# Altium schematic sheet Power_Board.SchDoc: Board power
size A3; Project: STM32MP15-DISCO; Date: Not used; ApprovedBy: Not used; CheckedBy: Not used; Author: Not used; CompanyName: STMicroelectronics; DrawnBy: Not used; Engineer: Not used; Organization: Not used; Address1: Not used; Address2: Not used; Address3: Not used; Address4: Not used; DocumentNumber: 5; Revision: Not used; SheetNumber: 5; SheetTotal: 17
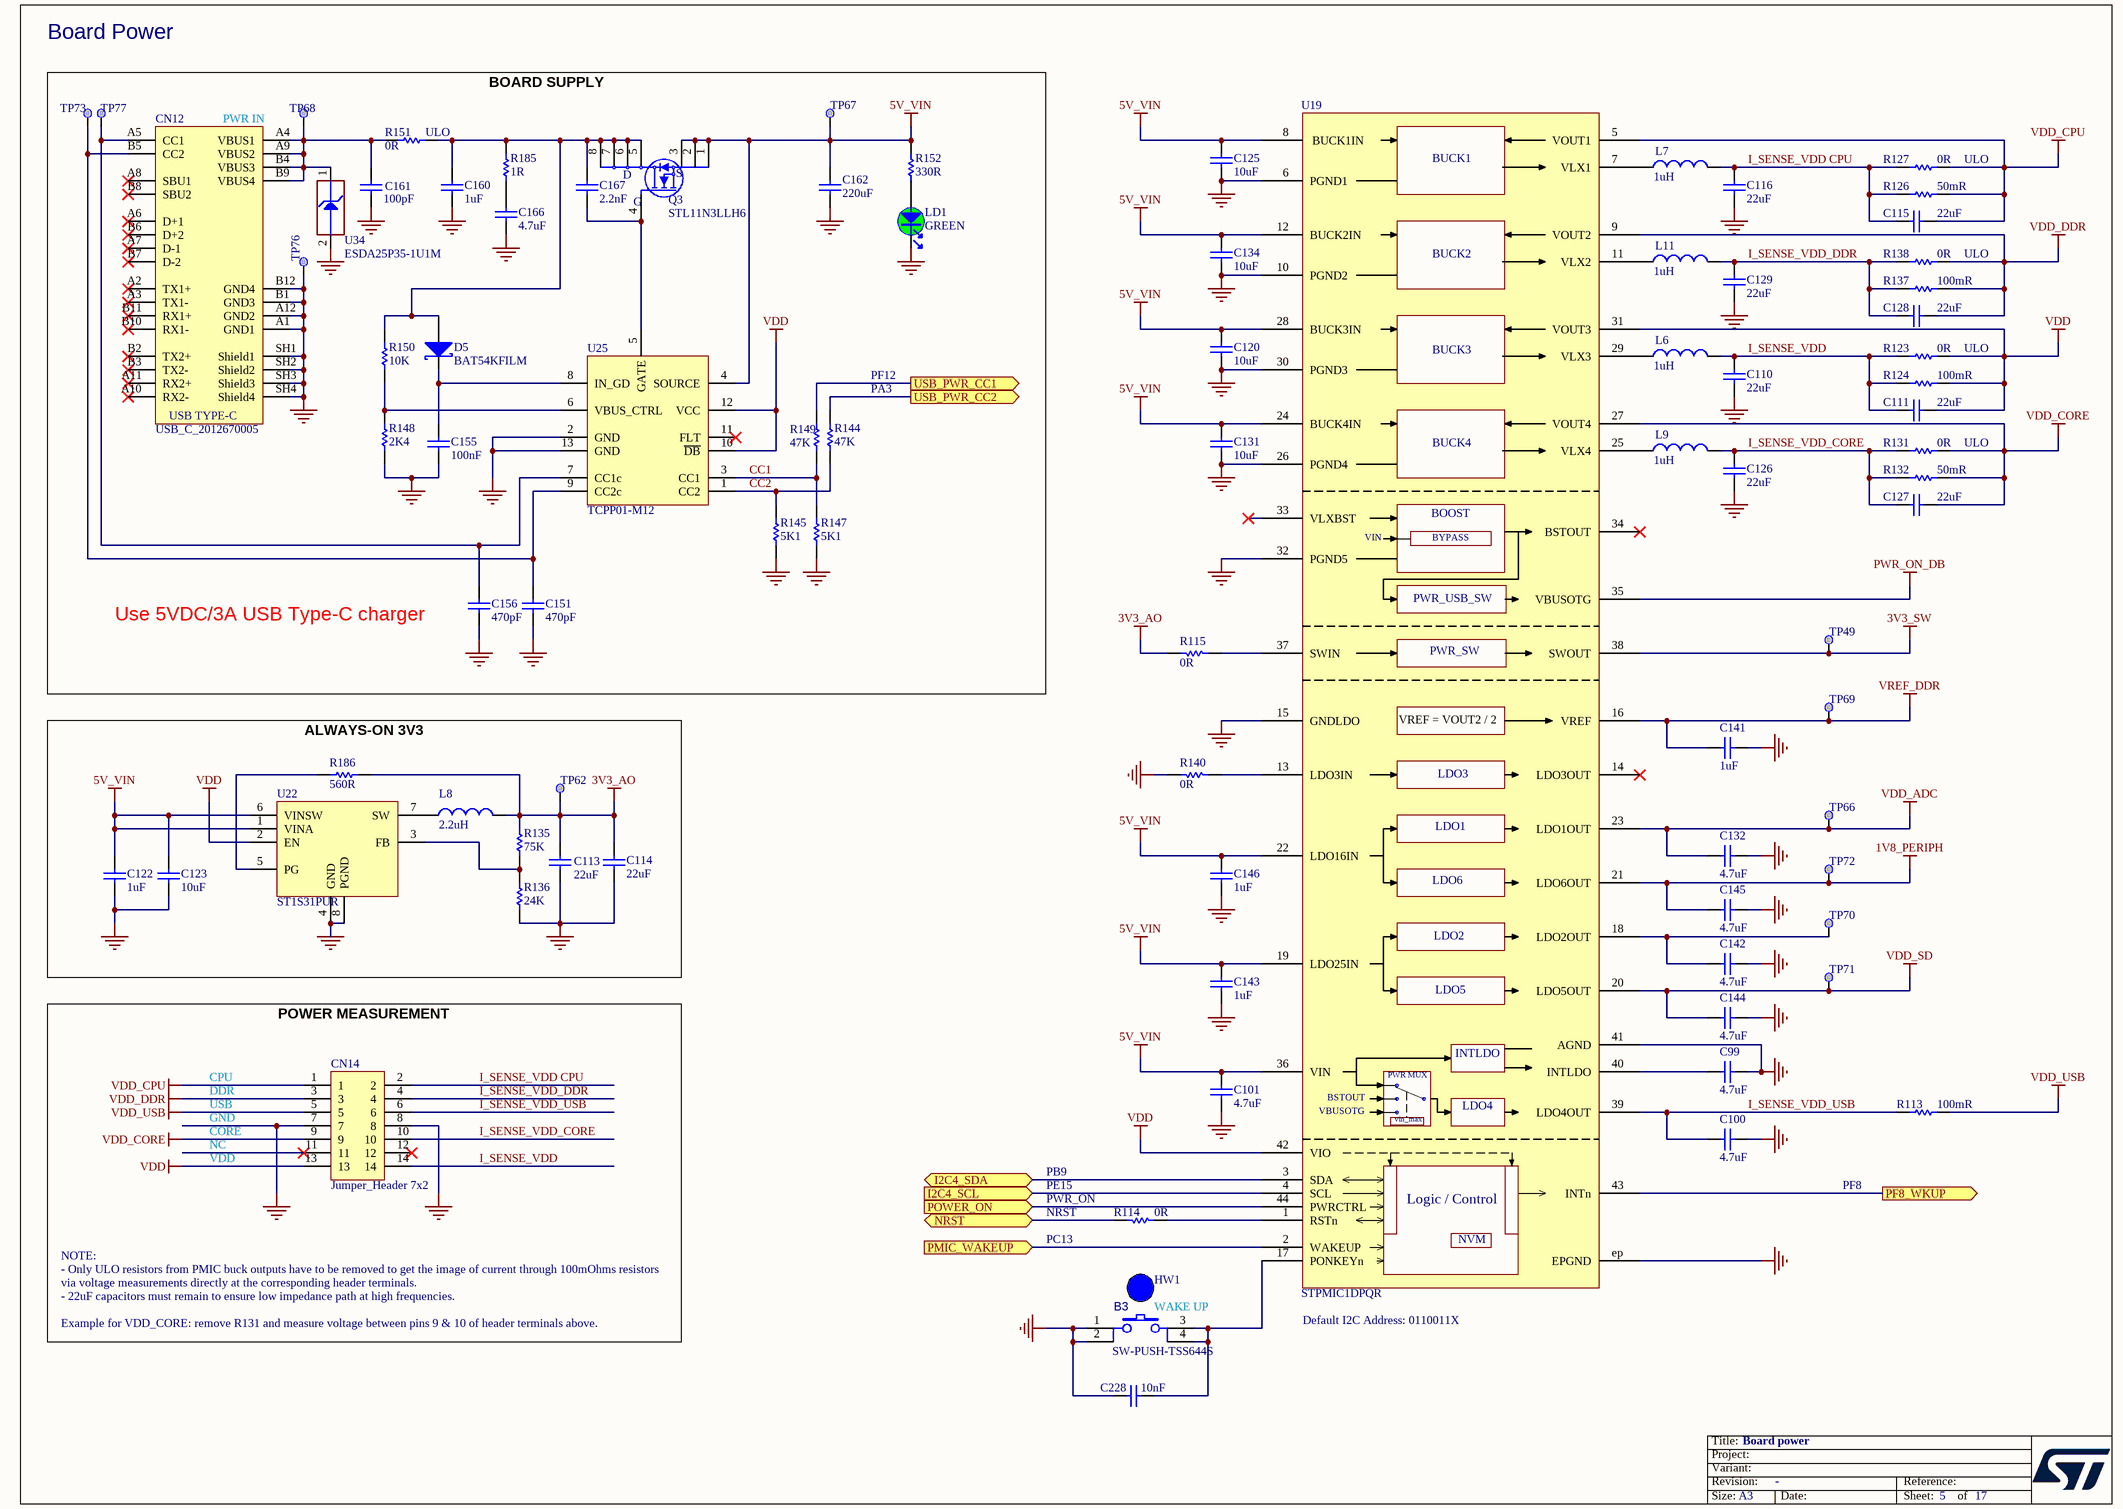
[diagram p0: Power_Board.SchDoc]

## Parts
B3  value SW-PUSH-TSS644S  [SWI_KNITTER_TSS644S]  (hidden comment: SW_PUSH_SMD)
C99  value 4.7uF  [C0402]  (hidden comment: Capacitor)
C100  value 4.7uF  [C0402]  (hidden comment: Capacitor)
C101  value 4.7uF  [C0402]  (hidden comment: Capacitor)
C110  value 22uF  [C0603]  (hidden comment: Capacitor)
C111  value 22uF  [C0603]  (hidden comment: Capacitor)
C113  value 22uF  [C0603]  (hidden comment: Capacitor)
C114  value 22uF  [C0603]  (hidden comment: Capacitor)
C115  value 22uF  [C0603]  (hidden comment: Capacitor)
C116  value 22uF  [C0603]  (hidden comment: Capacitor)
C120  value 10uF  [C0603]  (hidden comment: Capacitor)
C122  value 1uF  [C0402]  (hidden comment: Capacitor)
C123  value 10uF  [C0603]  (hidden comment: Capacitor)
C125  value 10uF  [C0603]  (hidden comment: Capacitor)
C126  value 22uF  [C0603]  (hidden comment: Capacitor)
C127  value 22uF  [C0603]  (hidden comment: Capacitor)
C128  value 22uF  [C0603]  (hidden comment: Capacitor)
C129  value 22uF  [C0603]  (hidden comment: Capacitor)
C131  value 10uF  [C0603]  (hidden comment: Capacitor)
C132  value 4.7uF  [C0402]  (hidden comment: Capacitor)
C134  value 10uF  [C0603]  (hidden comment: Capacitor)
C141  value 1uF  [C0402]  (hidden comment: Capacitor)
C142  value 4.7uF  [C0402]  (hidden comment: Capacitor)
C143  value 1uF  [C0402]  (hidden comment: Capacitor)
C144  value 4.7uF  [C0402]  (hidden comment: Capacitor)
C145  value 4.7uF  [C0402]  (hidden comment: Capacitor)
C146  value 1uF  [C0402]  (hidden comment: Capacitor)
C151  value 470pF  [C0402]  (hidden comment: Capacitor)
C155  value 100nF  [C0603]  (hidden comment: Capacitor)
C156  value 470pF  [C0402]  (hidden comment: Capacitor)
C160  value 1uF  [C0402]  (hidden comment: Capacitor)
C161  value 100pF  [C0402]  (hidden comment: Capacitor)
C162  value 220uF  [C1206_H1P6]  (hidden comment: Capacitor)
C166  value 4.7uF  [C0603]  (hidden comment: Capacitor)
C167  value 2.2nF  [C0603_H0P8]  (hidden comment: Capacitor)
C228  value 10nF  [C0402]  (hidden comment: Capacitor)
CN12  value USB_C_2012670005  [CON_USB-TYPEC_MOLEX_2012670005]  (hidden comment: USB_TYPE_C_Receptacle)
CN14  value Jumper_Header 7x2  [CON_SAMTEC_TSW-107-07-X-D]  (hidden comment: Header 7x2)
D5  value BAT54KFILM  [DIO_SOD523_1A_2K]  (hidden comment: SCHOTTKY_1A_2K)
HW1  Blue Hat  (value not drawn)  (mechanical)
L6  value 1uH  [IND_2520_TOKO_DFE252012P]  (hidden comment: IND_1uH_42mohm_3.2A)
L7  value 1uH  [IND_2520_TOKO_DFE252012P]  (hidden comment: IND_1uH_42mohm_3.2A)
L8  value 2.2uH  [IND_4025_WURTH_74404043022A]  (hidden comment: Inductor)
L9  value 1uH  [IND_2520_TOKO_DFE252012P]  (hidden comment: IND_1uH_42mohm_3.2A)
L11  value 1uH  [IND_2520_TOKO_DFE252012P]  (hidden comment: IND_1uH_42mohm_3.2A)
LD1  value GREEN  [LED_0603_GREEN]  (hidden comment: LED_green)
Q3  STL11N3LLH6  [MOS_POWERFLAT_3P3X3P3_P065]
R113  value 100mR  [R0603]  (hidden comment: Resistor)
R114  value 0R  [R0402]  (hidden comment: Resistor)
R115  value 0R  [R0402]  (hidden comment: Resistor)
R123  value 0R  [R0603]  (hidden comment: Resistor)
R124  value 100mR  [R0603]  (hidden comment: Resistor)
R126  value 50mR  [R0603]  (hidden comment: Resistor)
R127  value 0R  [R0603]  (hidden comment: Resistor)
R131  value 0R  [R0603]  (hidden comment: Resistor)
R132  value 50mR  [R0603]  (hidden comment: Resistor)
R135  value 75K  [R0402]  (hidden comment: Resistor)
R136  value 24K  [R0402]  (hidden comment: Resistor)
R137  value 100mR  [R0603]  (hidden comment: Resistor)
R138  value 0R  [R0603]  (hidden comment: Resistor)
R140  value 0R  [R0402]  (hidden comment: Resistor)
R144  value 47K  [R0402]  (hidden comment: Resistor)
R145  value 5K1  [R0402]  (hidden comment: Resistor)
R147  value 5K1  [R0402]  (hidden comment: Resistor)
R148  value 2K4  [R0402]  (hidden comment: Resistor)
R149  value 47K  [R0402]  (hidden comment: Resistor)
R150  value 10K  [R0402]  (hidden comment: Resistor)
R151  value 0R  [R0603]  (hidden comment: Resistor)
R152  value 330R  [R0402]  (hidden comment: Resistor)
R185  value 1R  [R0603]  (hidden comment: Resistor)
R186  value 560R  [R0402]  (hidden comment: Resistor)
TP49  Test Point  [TP_SMD_1MM]  (value not drawn)  (no BOM)
TP62  Test Point  [TP_SMD_1MM]  (value not drawn)  (no BOM)
TP66  Test Point  [TP_SMD_1MM]  (value not drawn)  (no BOM)
TP67  Test Point  [TP_SMD_1MM]  (value not drawn)  (no BOM)
TP68  Test Point  [TP_SMD_2MM]  (value not drawn)  (no BOM)
TP69  Test Point  [TP_SMD_1MM]  (value not drawn)  (no BOM)
TP70  Test Point  [TP_SMD_1MM]  (value not drawn)  (no BOM)
TP71  Test Point  [TP_SMD_1MM]  (value not drawn)  (no BOM)
TP72  Test Point  [TP_SMD_1MM]  (value not drawn)  (no BOM)
TP73  Test Point  [TP_SMD_1MM]  (value not drawn)  (no BOM)
TP76  Test Point  [TP_SMD_2MM]  (value not drawn)  (no BOM)
TP77  Test Point  [TP_SMD_1MM]  (value not drawn)  (no BOM)
U19  value STPMIC1DPQR  [ICC_WFQFN44-EPAD_5X6_P040]  (hidden comment: STPMU1)
U22  ST1S31PUR  [ICC_VFDFPN8-EPAD_3X3_P065]
U25  TCPP01-M12  [ICC_QFN12L-EPAD_3X3_P050]
U34  value ESDA25P35-1U1M  [ESD_QFN1610_2N_1K_2A]  (hidden comment: ESD-TRANSIL)

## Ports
I2C4_SCL (in), I2C4_SDA (bidir), NRST (bidir), PF8_WKUP (out), PMIC_WAKEUP (in), POWER_ON (in), USB_PWR_CC1 (out), USB_PWR_CC2 (out)

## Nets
1V8_PERIPH: C145.2 TP72.1 U19.21(LDO6OUT)
3V3_AO: C113.2 C114.2 L8.2 R115.1 R135.2 R186.2 TP62.1
3V3_SW: TP49.1 U19.38(SWOUT)
5V_VIN: C101.2 C120.2 C122.2 C123.2 C125.2 C131.2 C134.2 C143.2 C146.2 C162.1 Q3.1(S) Q3.2(S) Q3.3(S) R152.2 TP67.1 U19.8(BUCK1IN) U19.12(BUCK2IN) U19.19(LDO25IN) U19.22(LDO16IN) U19.24(BUCK4IN) U19.28(BUCK3IN) U19.36(VIN) U22.1(VINA) U22.6(VINSW) U25.4(SOURCE)
GND: B3.1 B3.2 C99.2 C100.1 C101.1 C110.1 C113.1 C114.1 C116.1 C120.1 C122.1 C123.1 C125.1 C126.1 C129.1 C131.1 C132.1 C134.1 C141.1 C142.1 C143.1 C144.1 C145.1 C146.1 C151.1 C155.2 C156.1 C160.2 C161.1 C162.2 C166.1 C228.1 CN12.A1(GND1) CN12.A12(GND2) CN12.B1(GND3) CN12.B12(GND4) CN12.SH1(Shield1) CN12.SH2(Shield2) CN12.SH3(Shield3) CN12.SH4(Shield4) CN14.7 CN14.8 LD1.2 R136.1 R140.1 R145.1 R147.1 R148.1 TP76.1 U19.6(PGND1) U19.10(PGND2) U19.15(GNDLDO) U19.26(PGND4) U19.30(PGND3) U19.32(PGND5) U19.41(AGND) U19.ep(EPGND) U22.4(GND) U22.8(PGND) U25.2(GND) U25.13(GND) U34.2(GND)
PWR_ON_DB: U19.35(VBUSOTG)
VDD: C111.2 CN14.13 R123.2 R124.2 U19.31(VOUT3) U19.42(VIO) U22.2(EN) U25.10(~{DB}) U25.12(VCC)
VDD_ADC: C132.2 TP66.1 U19.23(LDO1OUT)
VDD_CORE: C127.2 CN14.9 R131.2 R132.2 U19.27(VOUT4)
VDD_CPU: C115.2 CN14.1 R126.2 R127.2 U19.5(VOUT1)
VDD_DDR: C128.2 CN14.3 R137.2 R138.2 U19.9(VOUT2)
VDD_SD: C144.2 TP71.1 U19.20(LDO5OUT)
VDD_USB: CN14.5 R113.2
VREF_DDR: C141.2 TP69.1 U19.16(VREF)
CC1: R147.2 R149.1 U25.3(CC1)
CC2: R144.1 R145.2 U25.1(CC2)
I2C4_SCL: U19.4(SCL) ; port I2C4_SCL
I2C4_SDA: U19.3(SDA) ; port I2C4_SDA
I_SENSE_VDD: C110.2 C111.1 CN14.14 L6.2 R123.1 R124.1
I_SENSE_VDD CPU: C115.1 C116.2 CN14.2 L7.2 R126.1 R127.1
I_SENSE_VDD_CORE: C126.2 C127.1 CN14.10 L9.2 R131.1 R132.1
I_SENSE_VDD_DDR: C128.1 C129.2 CN14.4 L11.2 R137.1 R138.1
I_SENSE_VDD_USB: C100.2 CN14.6 R113.1 U19.39(LDO4OUT)
NRST: R114.1 ; port NRST
PF8_WKUP: U19.43(INTn) ; port PF8_WKUP
PMIC_WAKEUP: U19.2(WAKEUP) ; port PMIC_WAKEUP
POWER_ON: U19.44(PWRCTRL) ; port POWER_ON
USB_PWR_CC1: R149.2 ; port USB_PWR_CC1
USB_PWR_CC2: R144.2 ; port USB_PWR_CC2
NetB3_3: B3.3 B3.4 C228.2 U19.17(PONKEYn)
NetC99_1: C99.1 U19.40(INTLDO)
NetC142_2: C142.2 TP70.1 U19.18(LDO2OUT)
NetC151_2: C151.2 CN12.B5(CC2) TP73.1 U25.9(CC2c)
NetC155_1: C155.1 D5.2(K) U25.8(IN_GD)
NetC156_2: C156.2 CN12.A5(CC1) TP77.1 U25.7(CC1c)
NetC160_1: C160.1 C167.2 D5.1(A) Q3.5(D) Q3.6(D) Q3.7(D) Q3.8(D) R150.2 R151.2 R185.2
NetC161_2: C161.2 CN12.A4(VBUS1) CN12.A9(VBUS2) CN12.B4(VBUS3) CN12.B9(VBUS4) R151.1 TP68.1 U34.1(IO1)
NetC166_2: C166.2 R185.1
NetC167_1: C167.1 Q3.4(G) U25.5(GATE)
NetL6_1: L6.1 U19.29(VLX3)
NetL7_1: L7.1 U19.7(VLX1)
NetL8_1: L8.1 U22.7(SW)
NetL9_1: L9.1 U19.25(VLX4)
NetL11_1: L11.1 U19.11(VLX2)
NetLD1_1: LD1.1 R152.1
NetR114_2: R114.2 U19.1(RSTn)
NetR115_2: R115.2 U19.37(SWIN)
NetR135_1: R135.1 R136.2 U22.3(FB)
NetR140_2: R140.2 U19.13(LDO3IN)
NetR148_2: R148.2 R150.1 U25.6(VBUS_CTRL)
NetR186_1: R186.1 U22.5(PG)

Not connected (* = marked no-connect by the designer): CN12 A2(TX1+)* A3(TX1-)* A6(D+1)* A7(D-1)* A8(SBU1)* A10(RX2-)* A11(RX2+)* B2(TX2+)* B3(TX2-)* B6(D+2)* B7(D-2)* B8(SBU2)* B10(RX1-)* B11(RX1+)*; CN14 11* 12*; U19 14(LDO3OUT)* 33(VLXBST)* 34(BSTOUT)*; U25 11(FLT)*

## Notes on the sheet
- Board Power
- (near CN12) PWR IN
- (near R151) ULO
- ULO
- PF12
- PA3
- Use 5VDC/3A USB Type-C charger
- BOARD SUPPLY
- ALWAYS-ON 3V3
- CPU
- DDR
- USB
- GND
- VDD
- CORE
- NC
- PB9
- PE15
- PF8
- NRST
- (near R114) PWR_ON
- PC13
- NOTE:
  - Only ULO resistors from PMIC buck outputs have to be removed to get the image of current through 100mOhms resistors via voltage measurements directly at the corresponding header terminals.
  - 22uF capacitors must remain to ensure low impedance path at high frequencies.
  Example for VDD_CORE: remove R131 and measure voltage between pins 9 & 10 of header terminals above.
- (near B3) WAKE UP
- Default I2C Address: 0110011X
- (near CN14) POWER MEASUREMENT

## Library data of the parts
B3 = MCD-02417: Push Button, NO, 0.05A, 12V, 2.6N, SMD, 9.0x6.2mm, T=7.3mm, changeable caps KTSC-6xx; Part_Type: Misc; Manufacturer_Part_Number: TSS644S; Manufacturer: KNITTER-SWITCH; Part_Preference: Recommended; Component_Country_Of_Origin: China; ShowFields: YES; ID: 4523
C99-C101 C132 C142 C144 C145 = MCD-01356: Capacitor, MLCC, 4.7uF, 6V3, X5R, +/-20%, 0402, T=0.5mm; Manufacturer_Part_Number: GRM155R60J475ME47; Manufacturer: MURATA; Part_Preference: Recommended; Order_Code_RS: 814-5230; Component_Country_Of_Origin: Japan; ShowFields: YES; ID: 3456
C110 C116 C126 C129 = MCD-00100: Capacitor, MLCC, 22uF, 6V3, X5R, +/-20%, 0603, T=0.8mm; Manufacturer_Part_Number: GRM188R60J226MEA0J; Manufacturer: MURATA; Part_Preference: Recommended; Component_Country_Of_Origin: Japan; ShowFields: YES; ID: 2766
C111 C113-C115 C127 C128 = MCD-00100: Capacitor, MLCC, 22uF, 6V3, X5R, +/-20%, 0603, T=0.8mm; Part_Preference: Recommended; Manufacturer: MURATA; Manufacturer_Part_Number: GRM188R60J226MEA0J; Component_Country_Of_Origin: Japan; ShowFields: YES; ID: 2766
C120 C125 C131 C134 = MCD-00099: Capacitor, MLCC, 10uF, 10V, X5R, +/-10%, 0603, T=0.8mm; Manufacturer_Part_Number: GRM188R61A106KE69D; Manufacturer: MURATA; Part_Preference: Recommended; Order_Code_RS: 170-6168; Component_Country_Of_Origin: Japan; ShowFields: YES; ID: 2770
C122 = MCD-00095: Capacitor, MLCC, 1uF, 25V, X5R, +/-10%, 0402, T=0.5mm; Part_Preference: Recommended; Manufacturer: MURATA; Manufacturer_Part_Number: GRM155R61E105KA12; Order_Code_RS: 846-7287; Component_Country_Of_Origin: Japan; ShowFields: YES; ID: 2772
C123 = MCD-00099: Capacitor, MLCC, 10uF, 10V, X5R, +/-10%, 0603, T=0.8mm; Part_Preference: Recommended; Manufacturer: MURATA; Manufacturer_Part_Number: GRM188R61A106KE69D; Order_Code_RS: 170-6168; Component_Country_Of_Origin: Japan; ShowFields: YES; ID: 2770
C141 C143 C146 C160 = MCD-00095: Capacitor, MLCC, 1uF, 25V, X5R, +/-10%, 0402, T=0.5mm; Manufacturer_Part_Number: GRM155R61E105KA12; Manufacturer: MURATA; Part_Preference: Recommended; Order_Code_RS: 846-7287; Component_Country_Of_Origin: Japan; ShowFields: YES; ID: 2772
C151 C156 = MCD-00724: Capacitor, MLCC, 470pF, 50V, NPO, +/-5%, 0402, T=0.5mm; Manufacturer_Part_Number: CC0402JRNPO9BN471; Manufacturer: YAGEO; Part_Preference: Recommended; Order_Code_RS: 199-2186; Component_Country_Of_Origin: China; ShowFields: YES; ID: 3023
C155 = MCD-01099: Capacitor, MLCC, 100nF, 50V, X7R, +/-10%, 0603, T=0.8mm; Manufacturer_Part_Number: CC0603KRX7R9BB104; Manufacturer: YAGEO; Part_Preference: Recommended; BMS_Part_Number: 9142278; Order_Code_RS: 669-8767; Component_Country_Of_Origin: China; ShowFields: YES; ID: 3397
C161 = MCD-00205: Capacitor, MLCC, 100pF, 50V, NPO, +/-5%, 0402, T=0.5mm; Manufacturer_Part_Number: CC0402JRNPO9BN101; Manufacturer: YAGEO; Part_Preference: Recommended; Component_Country_Of_Origin: China; ShowFields: YES; ID: 2658
C162 = MCD-00104: Capacitor, MLCC, 220uF, 6V3, X5R, +/-20%, 1206, T=1.6mm; Manufacturer_Part_Number: GRM31CR60J227ME11; Manufacturer: MURATA; Part_Preference: Recommended; Order_Code_RS: 170-6396; Component_Country_Of_Origin: Japan; ShowFields: YES; ID: 2764
C166 = MCD-02196: Capacitor, MLCC, 4.7uF, 25V, X5R, +/-10%, 0603, T=0.8mm; Manufacturer_Part_Number: C1608X5R1E475K080AC; Manufacturer: TDK; Part_Preference: Recommended; Order_Code_RS: 9159158; Component_Country_Of_Origin: Unknown; ShowFields: YES; ID: 4296
C167 = MCD-02457: Capacitor, MLCC, 2.2nF, 50V, C0G/NPO, +/-5%, 0603, T=0,8mm; Part_Preference: Recommended; Manufacturer: YAGEO; Manufacturer_Part_Number: CC0603JRNPO9BN222; Order_Code_RS: 200-6484; Component_Country_Of_Origin: China; ShowFields: YES; ID: 4563
C228 = MCD-02198: Capacitor, MLCC, 10nF, 50V, X7R, +/-10%, 0402, T=0.5mm; Manufacturer_Part_Number: CC0402KRX7R9BB103; Manufacturer: YAGEO; Part_Preference: Recommended; Order_Code_RS: 6169644; Component_Country_Of_Origin: China; ShowFields: YES; ID: 4298
CN12 = MCD-02421: USB_TypeC, 24 pins, RA, SMD, T=3.71mm (USB Certified 3.1); Part_Type: Connector; Manufacturer_Part_Number: 2012670005; Manufacturer: MOLEX; Part_Preference: Recommended; Order_Code_RS: 176-8434; Component_Country_Of_Origin: Unknown; ShowFields: YES; ID: 4527
CN14 = MCD-02123: Header, 7x2, 2.54mm, VR, TH, T=5.84mm/2.54mm; Part_Preference: Recommended; Part_Type: Connector; Manufacturer: SAMTEC; Manufacturer_Part_Number: TSW-107-07-G-D; Component_Country_Of_Origin: China, Costa Rica, Malaysia, United States, Vietnam; ShowFields: YES; ID: 4223
D5 = MCD-01677: Small signal Schottky diodes; BMS_Part_Number: 9151123; Part_Preference: Recommended; Part_Type: Diode; Manufacturer: STMICROELECTRONICS; Manufacturer_HQ_COO: EU; Component_Country_Of_Origin: China; ShowFields: YES; ID: 3777
HW1 = MCD-02136: Switch hat, blue, For KTSC-62B; Part_Type: Misc; Part_Preference: Recommended; Manufacturer: APEM INC; Manufacturer_Part_Number: AKTSC62B; Order_Code_RS: 378-6779; Component_Country_Of_Origin: Unknown; ShowFields: YES; ID: 4236
L6 L7 L9 L11 = MCD-01122: Inductor, 1uH, +/-20%, 4.3A max, 0R042, 2520, T=1.2mm; Manufacturer_Part_Number: DFE252012P-1ROM=P2; Manufacturer: MURATA; Part_Preference: Recommended; Component_Country_Of_Origin: Japan; ShowFields: YES; ID: 3373
L8 = MCD-02242: Inductor, 2.2uH, +/-30%, 3,83A, 0R023, 4x4mm, T=2.5mm; Part_Preference: Recommended; Manufacturer: WURTH ELEKTRONIK; Manufacturer_Part_Number: 74404043022A; Component_Country_Of_Origin: Unknown; ShowFields: YES; ID: 4342
LD1 = MCD-00050: LED, Green, 0603; Part_Type: Display; Manufacturer_Part_Number: 19-213SYGC/S530-E2/TR8; Manufacturer: EVERLIGHT; Part_Preference: Forbidden; Component_Country_Of_Origin: China; ShowFields: YES; ID: 2542
Q3 = MCD-01810: N-channel 30 V, 6 mΩ typ, 11 A STripFET™ H6, Power MOSFET in a PowerFLAT™ 3.3x3.3 package; Part_Type: IC; Manufacturer: STMICROELECTRONICS; BMS_Part_Number: 9153561; Part_Preference: Recommended; Manufacturer_HQ_COO: EU; Component_Country_Of_Origin: China; ShowFields: YES; ID: 3910
R113 R124 R137 = MCD-02234: Resistor, 100mR, 0603, +/- 1%, 1/3W; Part_Preference: Recommended; Manufacturer: PANASONIC; Manufacturer_Part_Number: ERJ-3BWFR100V; Order_Code_RS: 763-8731; Component_Country_Of_Origin: Japan; ShowFields: YES; ID: 4334
R114 R115 R140 = MCD-00052: Resistor, 0R, 0402, +/-5%, 1/16W; Manufacturer_Part_Number: RC0402JR-070RL; Manufacturer: YAGEO; Part_Preference: Recommended; Order_Code_RS: 618-5804; Component_Country_Of_Origin: China; ShowFields: YES; ID: 2540
R123 R127 R131 R138 = MCD-00181: Resistor, 0R, 0603, +/- 0.5mR, 1/4W; Part_Preference: Recommended; Manufacturer: ROHM; Manufacturer_Part_Number: PMR03EZPJ000; Component_Country_Of_Origin: Philippines, Thailand; ShowFields: YES; ID: 2691
R126 R132 = MCD-02233: Resistor, 50mR, 0603, +/-1%, 1/3W; Part_Preference: Recommended; Manufacturer: PANASONIC; Manufacturer_Part_Number: ERJ-3BWFR050V; Order_Code_RS: RA; Component_Country_Of_Origin: Japan; ShowFields: YES; ID: 4333
R135 = MCD-00521: Resistor, 75K, 0402, +/-1%, 1/16W; Part_Preference: Recommended; Manufacturer: YAGEO; Manufacturer_Part_Number: RC0402FR-0775KL; Component_Country_Of_Origin: China; ShowFields: YES; ID: 3220
R136 = MCD-00435: Resistor, 24K, 0402, +/-1%, 1/16W; Part_Preference: Recommended; Manufacturer: YAGEO; Manufacturer_Part_Number: RC0402FR-0724KL; Component_Country_Of_Origin: China; ShowFields: YES; ID: 2845
R144 R149 = MCD-00063: Resistor, 47K, 0402, +/-1%, 1/16W; Manufacturer_Part_Number: RC0402FR-0747KL; Manufacturer: YAGEO; Part_Preference: Recommended; Component_Country_Of_Origin: China; ShowFields: YES; ID: 2528
R145 R147 = MCD-00333: Resistor, 5K1, 0402, +/-1%, 1/16W; Manufacturer_Part_Number: RC0402FR-075K1L; Manufacturer: YAGEO; Part_Preference: Recommended; Component_Country_Of_Origin: China; ShowFields: YES; ID: 2944
R148 = MCD-00433: Resistor, 2K4, 0402, +/-1%, 1/16W; Part_Preference: Recommended; Manufacturer: YAGEO; Manufacturer_Part_Number: RC0402FR-072K4L; Component_Country_Of_Origin: China; ShowFields: YES; ID: 2843
R150 = MCD-00053: Resistor, 10K, 0402, +/-1%, 1/16W; BMS_Part_Number: 9131590; Part_Preference: Recommended; Manufacturer: YAGEO; Manufacturer_Part_Number: RC0402FR-0710KL; Component_Country_Of_Origin: China; ShowFields: YES; ID: 2539
R151 = MCD-00181: Resistor, 0R, 0603, +/- 0.5mR, 1/4W; Manufacturer_Part_Number: PMR03EZPJ000; Manufacturer: ROHM; Part_Preference: Recommended; Component_Country_Of_Origin: Philippines, Thailand; ShowFields: YES; ID: 2691
R152 = MCD-00062: Resistor, 330R, 0402, +/-1%, 1/16W; Manufacturer_Part_Number: RC0402FR-07330RL; Manufacturer: YAGEO; Part_Preference: Recommended; Component_Country_Of_Origin: China; ShowFields: YES; ID: 2529
R185 = MCD-01512: Resistor, 1R, 0603, +/-1%, 1/10W; Part_Preference: Recommended; Manufacturer: YAGEO; Manufacturer_Part_Number: RC0603FR-071RL; Component_Country_Of_Origin: China; ShowFields: YES; ID: 3612
R186 = MCD-00489: Resistor, 560R, 0402, +/-1%, 1/16W; Part_Preference: Recommended; Manufacturer: YAGEO; Manufacturer_Part_Number: RC0402FR-07560RL; Component_Country_Of_Origin: China; ShowFields: YES; ID: 2789
TP49 TP62 TP66 TP67 TP69-TP73 TP77 = MCD-00074: Test Point 1mm; Part_Type: Misc; Part_Preference: Recommended; ShowFields: YES; ID: 2518
TP68 TP76 = MCD-00177: Test Point 2mm; Part_Type: Misc; Part_Preference: Recommended; ShowFields: YES; ID: 2690
U19 = MCD-02275: ST PMIC: 4 step-down +1 advanced boost SMPS, 6 LDOs, 2 pwr switches, DDR Vref, NVM option 'D' for IO@3.3V; Part_Preference: Recommended; Part_Type: IC; Manufacturer: STMICROELECTRONICS; Component_Country_Of_Origin: Philippines; ShowFields: YES; ID: 4375
U22 = MCD-02243: 3A DC step-down switching regulator 1,5MHz; Part_Preference: Recommended; Part_Type: IC; Manufacturer: STMICROELECTRONICS; Manufacturer_HQ_COO: EU; Component_Country_Of_Origin: Malaysia; ShowFields: YES; ID: 4343
U25 = MCD-01809: USB Type-C Port Protection for USB Power Delivery, PPS compliant; BMS_Part_Number: 9151145; Part_Preference: Recommended; Part_Type: IC; Manufacturer: STMICROELECTRONICS; Manufacturer_HQ_COO: EU; Component_Country_Of_Origin: Malaysia; ShowFields: YES; ID: 3909
U34 = MCD-01207: High power Transient voltage suppressor:25V/35A EOS and ESD transients protection.; BMS_Part_Number: 9179045; Part_Preference: Recommended; Part_Type: Diode; Manufacturer: STMICROELECTRONICS; Manufacturer_HQ_COO: EU; Component_Country_Of_Origin: China; ShowFields: YES; ID: 3289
